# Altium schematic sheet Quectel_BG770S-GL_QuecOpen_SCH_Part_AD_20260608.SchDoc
size A1
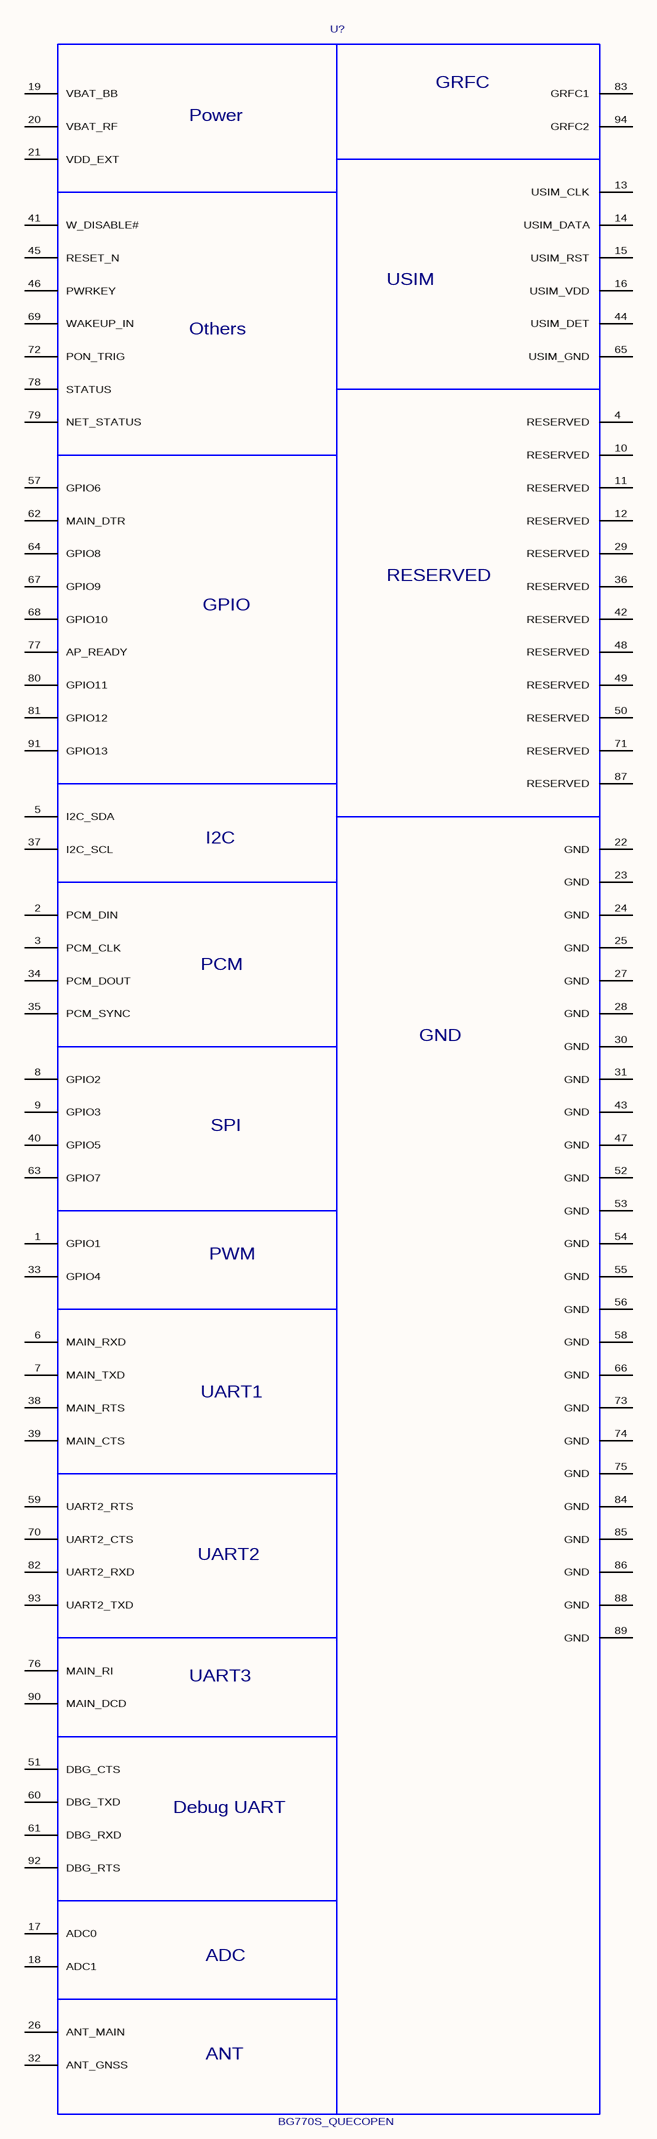
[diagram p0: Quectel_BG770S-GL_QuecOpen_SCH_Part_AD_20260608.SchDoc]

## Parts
U?  BG770S_QUECOPEN  [BG770S_QUECOPEN]

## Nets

Not connected (* = marked no-connect by the designer): U? 1(GPIO1) 2(PCM_DIN) 3(PCM_CLK) 4(RESERVED) 5(I2C_SDA) 6(MAIN_RXD) 7(MAIN_TXD) 8(GPIO2) 9(GPIO3) 10(RESERVED) 11(RESERVED) 12(RESERVED) 13(USIM_CLK) 14(USIM_DATA) 15(USIM_RST) 16(USIM_VDD) 17(ADC0) 18(ADC1) 19(VBAT_BB) 20(VBAT_RF) 21(VDD_EXT) 22(GND) 23(GND) 24(GND) 25(GND) 26(ANT_MAIN) 27(GND) 28(GND) 29(RESERVED) 30(GND) 31(GND) 32(ANT_GNSS) 33(GPIO4) 34(PCM_DOUT) 35(PCM_SYNC) 36(RESERVED) 37(I2C_SCL) 38(MAIN_RTS) 39(MAIN_CTS) 40(GPIO5) 41(W_DISABLE#) 42(RESERVED) 43(GND) 44(USIM_DET) 45(RESET_N) 46(PWRKEY) 47(GND) 48(RESERVED) 49(RESERVED) 50(RESERVED) 51(DBG_CTS) 52(GND) 53(GND) 54(GND) 55(GND) 56(GND) 57(GPIO6) 58(GND) 59(UART2_RTS) 60(DBG_TXD) 61(DBG_RXD) 62(MAIN_DTR) 63(GPIO7) 64(GPIO8) 65(USIM_GND) 66(GND) 67(GPIO9) 68(GPIO10) 69(WAKEUP_IN) 70(UART2_CTS) 71(RESERVED) 72(PON_TRIG) 73(GND) 74(GND) 75(GND) 76(MAIN_RI) 77(AP_READY) 78(STATUS) 79(NET_STATUS) 80(GPIO11) 81(GPIO12) 82(UART2_RXD) 83(GRFC1) 84(GND) 85(GND) 86(GND) 87(RESERVED) 88(GND) 89(GND) 90(MAIN_DCD) 91(GPIO13) 92(DBG_RTS) 93(UART2_TXD) 94(GRFC2)

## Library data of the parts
U? = BG770S_QUECOPEN: Part Description: BG770S-GL_QuecOpen 94PIN 14.9×12.9mm H2.1mm RO; Manufacturer: Quectel; Geometry.Height: 2.1mm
